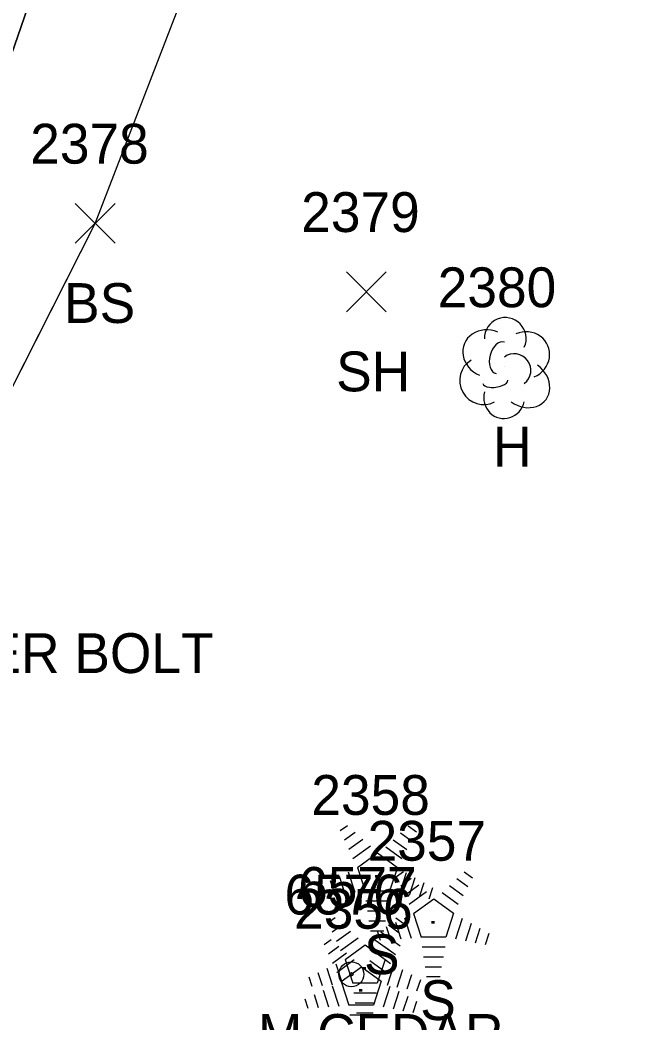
# Model space of a CAD drawing. Extents: x 1554668 to 1563881, y 831386 to 834374.
# Drawn here: x 1562176.7 to 1562207.7, y 832013.2 to 832063.6 of the extents above; entities that cross this region are included whole.
import ezdxf

# ---------------------------------------------------------------- set-up
doc = ezdxf.new("R2010")
doc.units = 0
for name, color, linetype in [('C_C', 7, 'Continuous'), ('C_I', 7, 'Continuous'), ('CBP', 7, 'Continuous'), ('L_A', 7, 'Continuous'), ('L_C', 7, 'Continuous'), ('L_I', 7, 'Continuous'), ('L_TIC', 7, 'Continuous'), ('LELB', 7, 'Continuous'), ('LTC', 7, 'Continuous'), ('LTD', 7, 'Continuous')]:
    doc.layers.add(name, color=color, linetype=linetype)

msp = doc.modelspace()

# ---------------------------------------------------------------- linework, layer by layer
at = {"layer": 'CBP'}
for radius in [0.625, 0.0833]:
    msp.add_circle((1562193.346, 832015.652), radius, dxfattribs=at)
at = {"layer": 'L_TIC'}
for points in [[(1562179.483, 832052.349), (1562181.483, 832054.349)], [(1562181.483, 832052.349), (1562179.483, 832054.349)], [(1562193.091, 832048.916), (1562195.091, 832050.916)], [(1562195.091, 832048.916), (1562193.091, 832050.916)]]:
    msp.add_lwpolyline(points, dxfattribs=at)
at = {"layer": 'LELB'}
for points in [[(1562199.916, 831969.319), (1562174.228, 831978.507), (1562157.189, 831989.733), (1562161.497, 832010.544), (1562167.08, 832026.881), (1562173.516, 832053.838), (1562186.033, 832090.068), (1562188.497, 832122.411), (1562199.146, 832168.617), (1562205.454, 832193.373), (1562206.668, 832210.489), (1562204.241, 832212.674)], [(1562199.916, 831969.319), (1562174.228, 831978.507), (1562157.189, 831989.733), (1562161.497, 832010.544), (1562167.08, 832026.881), (1562173.516, 832053.838), (1562186.033, 832090.068), (1562188.497, 832122.411), (1562199.146, 832168.617), (1562205.454, 832193.373), (1562206.668, 832210.489), (1562204.241, 832212.674)], [(1562199.916, 831969.319), (1562174.228, 831978.507), (1562157.189, 831989.733), (1562161.497, 832010.544), (1562167.08, 832026.881), (1562173.516, 832053.838), (1562186.033, 832090.068), (1562188.497, 832122.411), (1562199.146, 832168.617), (1562205.454, 832193.373), (1562206.668, 832210.489), (1562204.241, 832212.674)], [(1562199.919, 831969.317), (1562174.229, 831978.506), (1562157.192, 831989.737), (1562161.496, 832010.541), (1562167.08, 832026.877), (1562173.515, 832053.838), (1562186.031, 832090.065), (1562188.494, 832122.415), (1562199.144, 832168.622), (1562205.45, 832193.375), (1562206.664, 832210.489), (1562204.237, 832212.676)], [(1562167.08, 832026.877), (1562180.483, 832053.349), (1562194.086, 832088.601), (1562196.303, 832120.882), (1562207.54, 832166.92), (1562211.734, 832191.375), (1562215.854, 832206.885)], [(1562167.08, 832026.881), (1562180.484, 832053.351), (1562194.087, 832088.598), (1562196.306, 832120.88), (1562207.544, 832166.921), (1562211.738, 832191.373), (1562215.856, 832206.881)], [(1562167.08, 832026.881), (1562180.484, 832053.351), (1562194.087, 832088.598), (1562196.306, 832120.88), (1562207.544, 832166.921), (1562211.738, 832191.373), (1562215.856, 832206.881)], [(1562167.08, 832026.881), (1562180.484, 832053.351), (1562194.087, 832088.598), (1562196.306, 832120.88), (1562207.544, 832166.921), (1562211.738, 832191.373), (1562215.856, 832206.881)]]:
    msp.add_lwpolyline(points, dxfattribs=at)
at = {"layer": 'LTC'}
for p, q in [((1562192.788, 832022.862), (1562193.143, 832023.12)), ((1562196.187, 832023.103), (1562196.606, 832022.798)), ((1562192.998, 832022.397), (1562193.527, 832022.781)), ((1562193.208, 832021.931), (1562193.911, 832022.442)), ((1562195.445, 832022.406), (1562196.124, 832021.912)), ((1562195.816, 832022.754), (1562196.365, 832022.355)), ((1562193.417, 832021.465), (1562194.296, 832022.103)), ((1562195.073, 832022.058), (1562195.883, 832021.469)), ((1562193.642, 832021.01), (1562194.653, 832021.745)), ((1562194.653, 832021.745), (1562195.651, 832021.02)), ((1562193.642, 832021.01), (1562194.029, 832019.817)), ((1562195.651, 832021.02), (1562195.259, 832019.817)), ((1562192.276, 832020.358), (1562192.488, 832019.707)), ((1562192.732, 832020.575), (1562193.003, 832019.739)), ((1562193.187, 832020.791), (1562193.518, 832019.772)), ((1562195.609, 832020.561), (1562195.964, 832020.819)), ((1562196.088, 832020.749), (1562195.75, 832019.709)), ((1562195.819, 832020.096), (1562196.348, 832020.48)), ((1562196.533, 832020.499), (1562196.245, 832019.614)), ((1562198.636, 832020.453), (1562199.186, 832020.054)), ((1562199.008, 832020.801), (1562199.427, 832020.497)), ((1562191.821, 832020.142), (1562191.973, 832019.674)), ((1562196.028, 832019.63), (1562196.732, 832020.141)), ((1562196.977, 832020.249), (1562196.74, 832019.519)), ((1562197.421, 832019.998), (1562197.235, 832019.424)), ((1562198.266, 832020.105), (1562198.945, 832019.611)), ((1562195.259, 832019.817), (1562194.029, 832019.817)), ((1562196.238, 832019.164), (1562197.116, 832019.802)), ((1562196.463, 832018.709), (1562197.474, 832019.444)), ((1562197.474, 832019.444), (1562198.471, 832018.719)), ((1562197.894, 832019.756), (1562198.704, 832019.168)), ((1562195.221, 832019.317), (1562194.076, 832019.317)), ((1562192.171, 832018.243), (1562192.526, 832018.5)), ((1562195.137, 832018.817), (1562194.149, 832018.817)), ((1562195.57, 832018.483), (1562195.989, 832018.179)), ((1562196.008, 832018.49), (1562196.339, 832017.471)), ((1562196.463, 832018.709), (1562196.85, 832017.516)), ((1562198.471, 832018.719), (1562198.08, 832017.516)), ((1562198.909, 832018.448), (1562198.571, 832017.408)), ((1562192.381, 832017.778), (1562192.91, 832018.162)), ((1562195.053, 832018.317), (1562194.222, 832018.317)), ((1562194.642, 832017.84), (1562194.794, 832017.372)), ((1562195.097, 832018.057), (1562195.309, 832017.405)), ((1562195.198, 832018.135), (1562195.748, 832017.736)), ((1562195.553, 832018.274), (1562195.824, 832017.438)), ((1562199.353, 832018.197), (1562199.066, 832017.313)), ((1562199.798, 832017.947), (1562199.561, 832017.218)), ((1562191.979, 832017.147), (1562192.333, 832017.404)), ((1562192.591, 832017.312), (1562193.294, 832017.823)), ((1562192.8, 832016.846), (1562193.678, 832017.484)), ((1562194.97, 832017.817), (1562194.295, 832017.817)), ((1562194.456, 832017.438), (1562195.266, 832016.85)), ((1562194.828, 832017.787), (1562195.507, 832017.293)), ((1562195.377, 832017.387), (1562195.796, 832017.082)), ((1562198.08, 832017.516), (1562196.85, 832017.516)), ((1562200.242, 832017.697), (1562200.056, 832017.123)), ((1562192.188, 832016.681), (1562192.718, 832017.065)), ((1562193.025, 832016.391), (1562194.036, 832017.125)), ((1562194.036, 832017.125), (1562195.033, 832016.4)), ((1562195.006, 832017.039), (1562195.555, 832016.639)), ((1562198.042, 832017.016), (1562196.897, 832017.016)), ((1562192.398, 832016.215), (1562193.102, 832016.727)), ((1562192.608, 832015.749), (1562193.486, 832016.387)), ((1562193.025, 832016.391), (1562193.412, 832015.198)), ((1562194.264, 832016.342), (1562195.073, 832015.753)), ((1562194.635, 832016.69), (1562195.314, 832016.197)), ((1562195.033, 832016.4), (1562194.642, 832015.198)), ((1562197.958, 832016.516), (1562196.97, 832016.516)), ((1562192.115, 832015.955), (1562192.386, 832015.12)), ((1562192.57, 832016.172), (1562192.901, 832015.153)), ((1562192.832, 832015.294), (1562193.844, 832016.029)), ((1562193.844, 832016.029), (1562194.841, 832015.304)), ((1562195.471, 832016.13), (1562195.133, 832015.09)), ((1562195.916, 832015.879), (1562195.628, 832014.995)), ((1562197.874, 832016.016), (1562197.043, 832016.016)), ((1562191.204, 832015.522), (1562191.356, 832015.054)), ((1562191.659, 832015.739), (1562191.871, 832015.087)), ((1562196.36, 832015.629), (1562196.123, 832014.9)), ((1562196.804, 832015.379), (1562196.618, 832014.805)), ((1562197.791, 832015.516), (1562197.116, 832015.516)), ((1562191.922, 832014.859), (1562192.193, 832014.024)), ((1562192.378, 832015.075), (1562192.708, 832014.056)), ((1562192.832, 832015.294), (1562193.219, 832014.101)), ((1562194.642, 832015.198), (1562193.412, 832015.198)), ((1562194.841, 832015.304), (1562194.45, 832014.101)), ((1562195.278, 832015.033), (1562194.94, 832013.994)), ((1562191.011, 832014.426), (1562191.163, 832013.958)), ((1562191.467, 832014.642), (1562191.678, 832013.991)), ((1562194.604, 832014.698), (1562193.459, 832014.698)), ((1562195.723, 832014.783), (1562195.435, 832013.898)), ((1562196.168, 832014.533), (1562195.93, 832013.803)), ((1562194.45, 832014.101), (1562193.219, 832014.101)), ((1562194.52, 832014.198), (1562193.532, 832014.198)), ((1562196.612, 832014.282), (1562196.425, 832013.708)), ((1562194.411, 832013.601), (1562193.267, 832013.601)), ((1562194.436, 832013.698), (1562193.605, 832013.698))]:
    msp.add_line(p, q, dxfattribs=at)
at = {"layer": 'LTD'}
msp.add_line((1562201.021, 832046.14), (1562201.021, 832046.14), dxfattribs=at)
msp.add_line((1562201.021, 832046.14), (1562201.021, 832046.14), dxfattribs=at)
msp.add_arc((1562201.068, 832047.574), 1.047, 335.5272, 180.9563, dxfattribs=at)
for centre, major_axis, ratio, start_param, end_param in [((1562200.23, 832046.807), (1.21, -0.512), 0.895232, 1.570796, 4.712389), ((1562202.063, 832046.724), (-1.141, -0.483), 0.949671, 1.570796, 4.712389), ((1562200.813, 832046.599), (-0.208, -0.792), 0.645439, 3.141593, 6.283185), ((1562201.522, 832045.974), (-0.5, 0.667), 0.989748, 3.141593, 6.283185), ((1562199.938, 832045.432), (0.584, -1.042), 0.959034, 3.141593, 6.283185), ((1562202.022, 832045.307), (-1.09, 0.792), 0.841452, 1.570796, 4.712389), ((1562200.563, 832045.39), (-0.625, -0.083), 0.423636, 0, 3.141593), ((1562201.022, 832044.64), (0.265, 1.061), 0.942809, 1.570796, 4.712389)]:
    msp.add_ellipse(centre, major_axis=major_axis, ratio=ratio, start_param=start_param, end_param=end_param, dxfattribs=at)

# ---------------------------------------------------------------- texts
at = {"layer": 'C_C'}
msp.add_text("TIE=17.21' TOP CENTER BOLT", height=2, dxfattribs=at).set_placement((1562147.793, 832030.774))
at = {"layer": 'C_I'}
msp.add_text('6576', height=2, dxfattribs=at).set_placement((1562189.984, 832018.652))
at = {"layer": 'L_A'}
for s, p in [('BS', (1562178.924, 832048.349)), ('SH', (1562192.579, 832044.916)), ('H', (1562200.455, 832041.14)), ('S', (1562193.979, 832015.654)), ('S', (1562196.8, 832013.353))]:
    msp.add_text(s, height=2, dxfattribs=at).set_placement(p)
at = {"layer": 'L_C'}
msp.add_text('M.CEDAR', height=2, dxfattribs=at).set_placement((1562188.648, 832011.654))
at = {"layer": 'L_I'}
for s, p in [('2378', (1562177.223, 832056.349)), ('2379', (1562190.823, 832052.916)), ('2380', (1562197.675, 832049.14)), ('2358', (1562191.333, 832023.654)), ('2357', (1562194.154, 832021.353)), ('6577', (1562190.669, 832019.035)), ('2356', (1562190.469, 832017.938))]:
    msp.add_text(s, height=2, dxfattribs=at).set_placement(p)
at = {"layer": 'LTC'}
for p in [(1562194.536, 832020.758), (1562197.357, 832018.457), (1562193.919, 832016.139), (1562193.726, 832015.042)]:
    msp.add_text('.', height=1.037, rotation=270, dxfattribs=at).set_placement(p)

doc.saveas('drawing.dxf')
